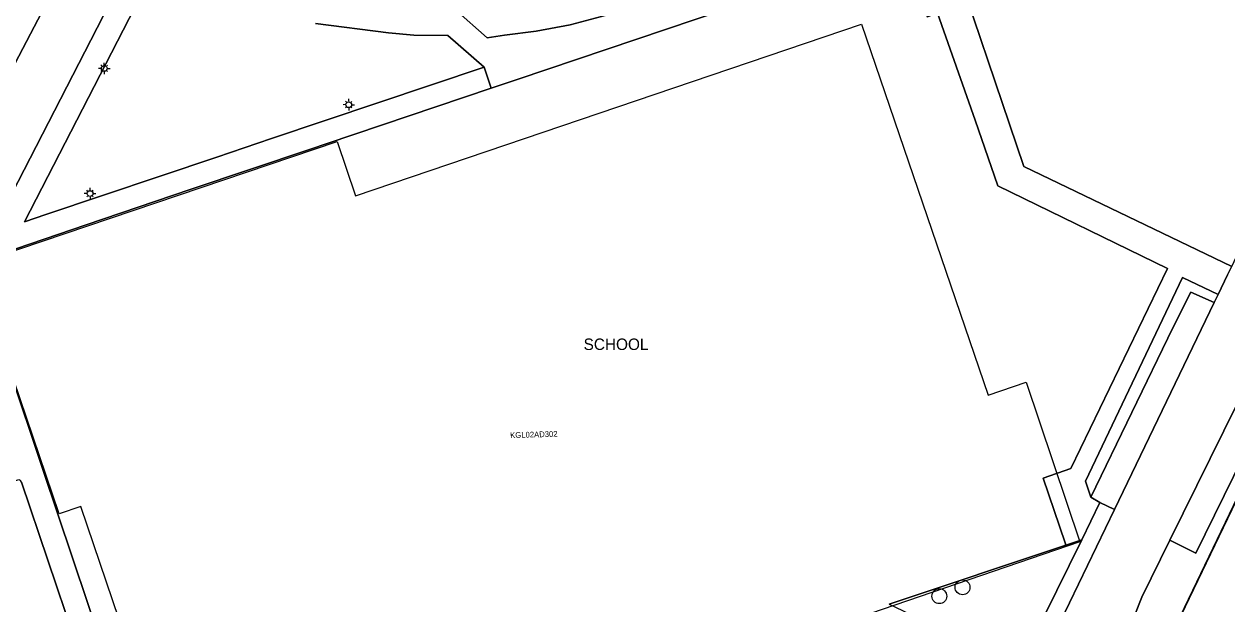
# Model space of a CAD drawing. Extents: x 124901 to 125496, y 515369 to 515789.
# Drawn here: x 125170.8 to 125275.6, y 515559.7 to 515610.2 of the extents above; entities that cross this region are included whole.
import ezdxf

# ---------------------------------------------------------------- set-up
doc = ezdxf.new("R2010")
doc.units = 0
for name, color, linetype in [('Lichtmast', 7, 'Continuous'), ('Onbegroeid terrein', 7, 'Continuous'), ('Parkeren', 7, 'Continuous'), ('Perceelnummers', 7, 'Continuous'), ('Perceelsgrenzen', 7, 'Continuous'), ('Putten', 7, 'Continuous'), ('Teksten', 7, 'Continuous'), ('Vegetatie', 7, 'Continuous'), ('Voetpad', 7, 'Continuous'), ('Wegen lokale weg', 7, 'Continuous')]:
    doc.layers.add(name, color=color, linetype=linetype)

msp = doc.modelspace()

# ---------------------------------------------------------------- linework, layer by layer
at = {"layer": 'Lichtmast'}
for p, q in [((125177.81, 515606.64), (125177.81, 515606.84)), ((125177.51, 515606.34), (125177.31, 515606.34)), ((125177.59, 515606.56), (125177.52, 515606.63)), ((125177.59, 515606.13), (125177.52, 515606.06)), ((125177.81, 515606.04), (125177.81, 515605.84)), ((125178.02, 515606.56), (125178.09, 515606.63)), ((125178.02, 515606.13), (125178.09, 515606.06)), ((125178.11, 515606.34), (125178.31, 515606.34)), ((125199.11, 515603.49), (125199.11, 515603.68)), ((125198.81, 515603.19), (125198.61, 515603.18)), ((125198.9, 515602.97), (125198.82, 515602.9)), ((125198.9, 515603.4), (125198.83, 515603.47)), ((125199.11, 515602.89), (125199.11, 515602.68)), ((125199.32, 515603.4), (125199.39, 515603.47)), ((125199.32, 515602.97), (125199.39, 515602.9)), ((125199.41, 515603.18), (125199.61, 515603.18)), ((125176.27, 515595.44), (125176.07, 515595.44)), ((125176.35, 515595.66), (125176.28, 515595.73)), ((125176.35, 515595.23), (125176.28, 515595.16)), ((125176.57, 515595.74), (125176.57, 515595.94)), ((125176.78, 515595.66), (125176.85, 515595.73)), ((125176.78, 515595.23), (125176.85, 515595.16)), ((125176.87, 515595.44), (125177.07, 515595.44)), ((125176.57, 515595.14), (125176.57, 515594.94))]:
    msp.add_line(p, q, dxfattribs=at)
for centre in [(125177.81, 515606.34), (125199.11, 515603.18), (125176.57, 515595.44)]:
    msp.add_circle(centre, 0.25, dxfattribs=at)
at = {"layer": 'Onbegroeid terrein'}
for points in [[(125247.46, 515616.75), (125213.78, 515605.38), (125211.52, 515604.62), (125197.24, 515599.79), (125195.77, 515599.3), (125185.3, 515595.81), (125176.22, 515592.73), (125166.42, 515589.39), (125172.49, 515571.33), (125177.63, 515556.03)], [(125246.19, 515559.68), (125261.59, 515564.82), (125261.52, 515565.02), (125259.61, 515570.67), (125262.01, 515571.5), (125270.45, 515588.93), (125255.66, 515596.11), (125253.67, 515601.84), (125250.39, 515611.14)]]:
    msp.add_lwpolyline(points, dxfattribs=at)
msp.add_lwpolyline([(125286.39, 515550.48), (125287.28, 515552.33), (125285.12, 515553.38), (125276.89, 515557.33), (125279.14, 515561.97), (125279.58, 515561.75), (125280.85, 515564.41), (125278.06, 515565.76), (125280.2, 515570.2), (125282.34, 515574.64), (125284.5, 515579.14), (125280.81, 515577.9), (125271.58, 515558.68), (125276.42, 515556.36), (125284.63, 515552.42), (125284.18, 515551.55), (125285.04, 515551.13)], close=True, dxfattribs=at)
at = {"layer": 'Parkeren'}
msp.add_lwpolyline([(125250.1, 515623.08), (125232.98, 515617.24), (125226.63, 515615.07), (125223.57, 515614.08), (125220.81, 515613.26), (125217.87, 515612.48), (125215.07, 515611.96), (125212.35, 515611.61), (125208.42, 515611.43), (125211.16, 515609.01), (125212.69, 515609.24), (125215.44, 515609.59), (125218.39, 515610.13), (125221.46, 515610.95), (125224.28, 515611.78), (125227.39, 515612.79), (125250.18, 515620.44)], dxfattribs=at)
for points in [[(125178.19, 515612.28), (125174.82, 515614.02), (125174.39, 515614.45), (125174.34, 515615.05), (125163.07, 515593.54), (125163.4, 515593.93), (125163.87, 515594.1), (125164.43, 515594), (125167.81, 515592.25), (125167.97, 515592.21), (125168.09, 515592.26), (125168.16, 515592.36), (125178.25, 515611.92), (125178.3, 515612.08), (125178.28, 515612.2)], [(125274.51, 515585.95), (125272.47, 515586.86), (125270.9, 515583.75), (125263.76, 515568.99), (125264.53, 515568.55), (125265.82, 515567.93)], [(125270.65, 515565.25), (125272.9, 515564.14), (125281.09, 515580.78), (125278.85, 515581.89)], [(125165.42, 515569.89), (125165.57, 515569.45), (125170.82, 515553.85), (125171.14, 515553.96), (125171.03, 515554.24), (125171.16, 515554.84), (125171.75, 515555.29), (125175.06, 515556.41), (125175.18, 515556.49), (125175.21, 515556.6), (125175.18, 515556.72), (125170.59, 515570.31), (125170.5, 515570.45), (125170.4, 515570.5), (125170.26, 515570.48), (125166.66, 515569.27), (125166.2, 515569.18), (125165.65, 515569.44)]]:
    msp.add_lwpolyline(points, close=True, dxfattribs=at)
at = {"layer": 'Perceelsgrenzen'}
for points in [[(125173.87, 515567.55), (125166.47, 515589.3), (125198.09, 515599.99), (125199.69, 515595.26), (125243.78, 515610.19), (125254.8, 515577.89), (125258.12, 515579.03), (125262.79, 515565.1), (125211.3, 515547.48), (125216.91, 515544.77), (125221.76, 515542.43), (125226.61, 515540.09), (125231.53, 515537.72), (125236.49, 515535.32), (125230.63, 515523.2), (125224.88, 515511.27), (125219.87, 515513.69), (125215.02, 515516.03), (125210.15, 515518.38), (125205.29, 515520.72), (125198.73, 515523.89), (125209.95, 515547.02), (125185.77, 515538.74), (125175.76, 515568.19)], [(125211.3, 515547.48), (125209.95, 515547.02), (125185.77, 515538.74), (125175.76, 515568.19), (125173.87, 515567.55), (125166.47, 515589.3), (125198.09, 515599.99), (125199.69, 515595.26), (125243.78, 515610.19), (125254.8, 515577.89), (125258.12, 515579.03), (125262.79, 515565.1)]]:
    msp.add_lwpolyline(points, close=True, dxfattribs=at)
msp.add_lwpolyline([(125286.81, 515551.36), (125271.62, 515558.71), (125280.85, 515577.9)], dxfattribs=at)
msp.add_lwpolyline([(125286.81, 515551.36), (125271.62, 515558.71), (125280.85, 515577.9)], dxfattribs=at)
at = {"layer": 'Putten'}
for centre in [(125252.58, 515561.15), (125250.56, 515560.38)]:
    msp.add_circle(centre, 0.65, dxfattribs=at)
at = {"layer": 'Vegetatie'}
for points in [[(125285.28, 515608.28), (125267.57, 515616.68), (125258.97, 515620.82), (125251.03, 515618.15), (125257.93, 515597.81), (125276.03, 515589.1), (125276.69, 515590.46), (125277.06, 515591.23), (125278.85, 515594.84), (125284.02, 515605.62)], [(125274.51, 515585.95), (125274.85, 515586.65), (125271.75, 515588.14), (125263.3, 515570.4), (125263.76, 515568.99), (125270.9, 515583.75), (125272.47, 515586.86)], [(125262.98, 515565.29), (125261.59, 515564.82), (125246.19, 515559.68), (125249.11, 515558.28), (125257.51, 515554.23)]]:
    msp.add_lwpolyline(points, close=True, dxfattribs=at)
for points in [[(125191.21, 515611.49), (125188.8, 515612.29), (125185.77, 515613.52), (125184.83, 515613.95), (125182.3, 515615.17), (125181.49, 515613.64), (125170.85, 515592.98), (125172.73, 515593.61), (125187.62, 515598.62), (125192.38, 515600.23), (125210.9, 515606.46)], [(125210.9, 515606.46), (125207.75, 515609.21), (125204.79, 515609.24), (125202.57, 515609.45), (125196.2, 515610.25)]]:
    msp.add_lwpolyline(points, dxfattribs=at)
at = {"layer": 'Voetpad'}
for points in [[(125250.18, 515620.44), (125227.39, 515612.79), (125224.28, 515611.78), (125221.46, 515610.95), (125218.39, 515610.13), (125215.44, 515609.59), (125212.69, 515609.24), (125211.16, 515609.01), (125208.42, 515611.43), (125205.24, 515611.43), (125202.19, 515611.63), (125199.25, 515611.98), (125196.3, 515612.55), (125192.87, 515613.42), (125190.09, 515614.26), (125186.13, 515615.69), (125180.84, 515618.29), (125168.6, 515624.58)], [(125196.2, 515610.25), (125202.57, 515609.45), (125204.79, 515609.24), (125207.75, 515609.21), (125210.9, 515606.46), (125211.52, 515604.62), (125213.78, 515605.38), (125247.46, 515616.75), (125251.03, 515618.15), (125258.97, 515620.82), (125267.57, 515616.68)], [(125177.63, 515556.03), (125172.49, 515571.33), (125166.42, 515589.39), (125176.22, 515592.73), (125185.3, 515595.81), (125195.77, 515599.3), (125197.24, 515599.79), (125211.52, 515604.62), (125210.9, 515606.46), (125192.38, 515600.23), (125187.62, 515598.62), (125172.73, 515593.61), (125170.85, 515592.98), (125181.49, 515613.64)], [(125178.25, 515611.92), (125168.16, 515592.36)], [(125170.59, 515570.31), (125175.18, 515556.72)], [(125287.12, 515533.63), (125269.12, 515542.27), (125271.45, 515547.13), (125258.77, 515553.31), (125265.82, 515567.93), (125264.53, 515568.55), (125262.98, 515565.29), (125257.51, 515554.23), (125249.11, 515558.28), (125248.71, 515556.39), (125268.55, 515546.84), (125266.36, 515542.26), (125286.74, 515532.49)]]:
    msp.add_lwpolyline(points, dxfattribs=at)
for points in [[(125276.03, 515589.1), (125257.93, 515597.81), (125251.03, 515618.15), (125247.46, 515616.75), (125249.51, 515610.84), (125250.39, 515611.14), (125253.67, 515601.84), (125255.66, 515596.11), (125270.45, 515588.93), (125262.01, 515571.5), (125259.61, 515570.67), (125261.52, 515565.02), (125261.59, 515564.82), (125262.98, 515565.29), (125264.53, 515568.55), (125263.76, 515568.99), (125263.3, 515570.4), (125271.75, 515588.14), (125274.85, 515586.65), (125275.67, 515588.36)], [(125274.21, 515551.8), (125276.42, 515556.36), (125271.58, 515558.68), (125280.81, 515577.9), (125284.5, 515579.14), (125285.19, 515580.58), (125279.6, 515583.41), (125278.85, 515581.89), (125281.09, 515580.78), (125272.9, 515564.14), (125270.65, 515565.25), (125268.21, 515560.28), (125267.59, 515558.77), (125267.39, 515558.19), (125267.38, 515557.48), (125267.45, 515556.93), (125267.72, 515556.08), (125267.98, 515555.5), (125268.37, 515554.97), (125268.71, 515554.56), (125269.91, 515553.88)]]:
    msp.add_lwpolyline(points, close=True, dxfattribs=at)
at = {"layer": 'Wegen lokale weg'}
msp.add_lwpolyline([(125169.88, 515621.52), (125170.07, 515621.21), (125170.29, 515620.07), (125170.23, 515618.72), (125169.89, 515617.63), (125169.76, 515617.39), (125156.7, 515592.14), (125161.2, 515589.81), (125162.08, 515591.57), (125163.07, 515593.54), (125174.34, 515615.05), (125174.48, 515615.38), (125175.12, 515616.24), (125176.14, 515617.12), (125177.26, 515617.7)], close=True, dxfattribs=at)
for points in [[(125275.67, 515588.36), (125274.85, 515586.65), (125274.51, 515585.95), (125265.82, 515567.93), (125258.77, 515553.31), (125271.45, 515547.13), (125289.4, 515538.38)], [(125283.24, 515547.41), (125274.21, 515551.8), (125269.91, 515553.88), (125268.71, 515554.56), (125268.37, 515554.97), (125267.98, 515555.5), (125267.72, 515556.08), (125267.45, 515556.93), (125267.38, 515557.48), (125267.39, 515558.19), (125267.59, 515558.77), (125268.21, 515560.28), (125270.65, 515565.25), (125278.85, 515581.89)]]:
    msp.add_lwpolyline(points, dxfattribs=at)

# ---------------------------------------------------------------- texts
at = {"layer": 'Perceelnummers'}
msp.add_text('KGL02AD302', height=0.5, rotation=1.6324, dxfattribs=at).set_placement((125213.18, 515574.15))
at = {"layer": 'Teksten'}
msp.add_text('SCHOOL', height=1, dxfattribs=at).set_placement((125219.57, 515581.82))

doc.saveas('drawing.dxf')
